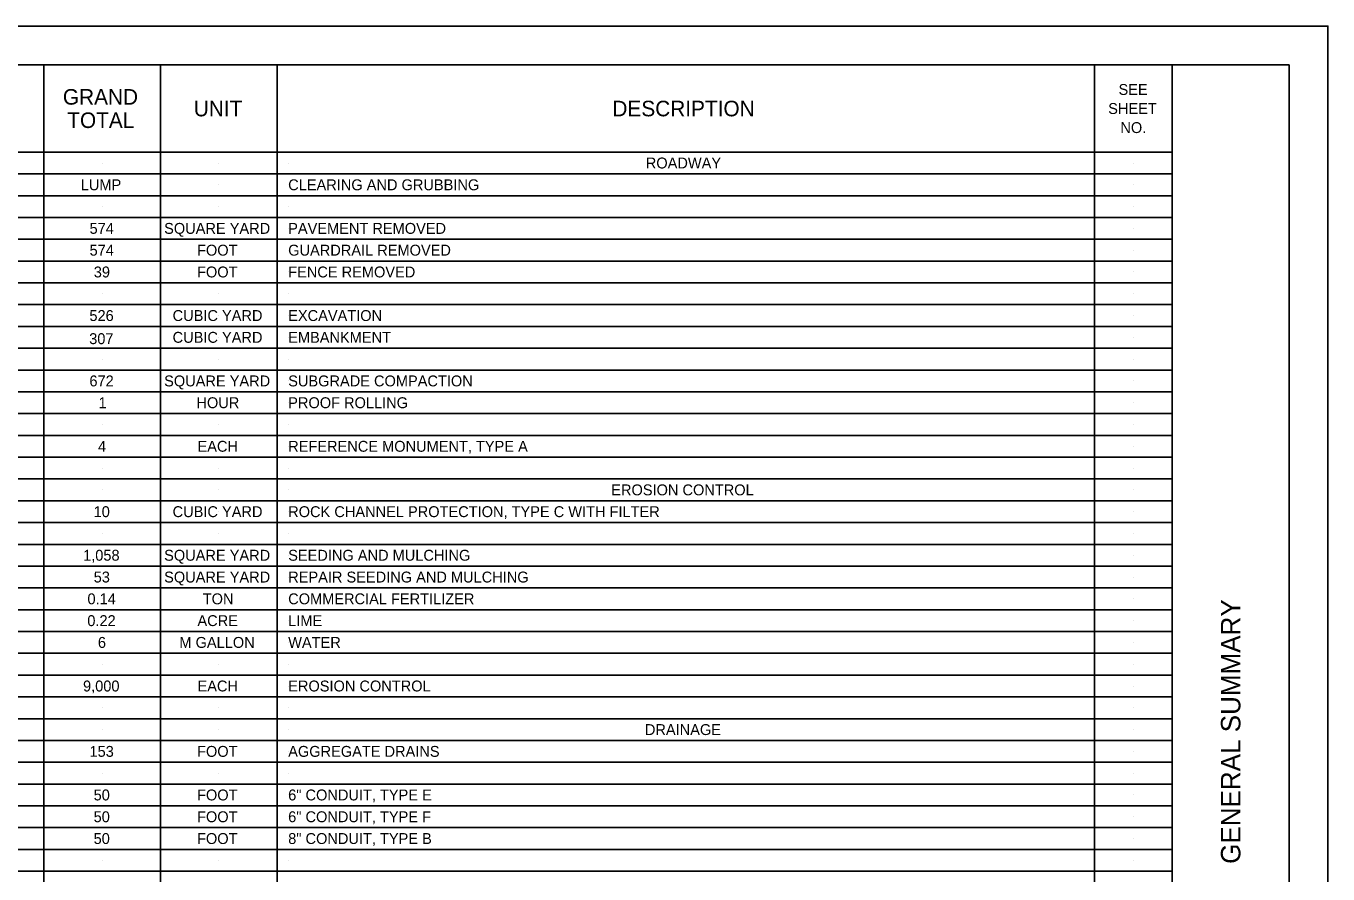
# Model space of a CAD drawing. Extents: x 0 to 34, y 0 to 22.
# Drawn here: x 17.27 to 34, y 11.1 to 22 of the extents above; entities that cross this region are included whole.
import ezdxf

# ---------------------------------------------------------------- set-up
doc = ezdxf.new("R2010")
doc.units = 0
for name, color, linetype in [('RD_P_Text', 7, 'Continuous'), ('SC_Scratch1', 7, 'Continuous'), ('SH_Border', 7, 'Continuous'), ('SH_Cut_Line', 7, 'Continuous'), ('SH_Data', 7, 'Continuous')]:
    doc.layers.add(name, color=color, linetype=linetype)

msp = doc.modelspace()

# ---------------------------------------------------------------- linework, layer by layer
at = {"layer": 'SC_Scratch1'}
for p, q in [((18.25, 20.24), (18.25, 20.24)), ((19.75, 20.24), (19.75, 20.24)), ((20.64, 20.24), (20.64, 20.24)), ((31.5, 20.24), (31.5, 20.24)), ((18.25, 19.96), (18.25, 19.96)), ((19.75, 19.96), (19.75, 19.96)), ((20.64, 19.96), (20.64, 19.96)), ((31.5, 19.96), (31.5, 19.96)), ((18.25, 19.68), (18.25, 19.68)), ((19.75, 19.68), (19.75, 19.68)), ((20.64, 19.68), (20.64, 19.68)), ((31.5, 19.68), (31.5, 19.68)), ((18.25, 19.4), (18.25, 19.4)), ((19.75, 19.4), (19.75, 19.4)), ((20.64, 19.4), (20.64, 19.4)), ((31.5, 19.4), (31.5, 19.4)), ((18.25, 19.12), (18.25, 19.12)), ((19.75, 19.12), (19.75, 19.12)), ((20.64, 19.12), (20.64, 19.12)), ((31.5, 19.12), (31.5, 19.12)), ((18.25, 18.84), (18.25, 18.84)), ((19.75, 18.84), (19.75, 18.84)), ((20.64, 18.84), (20.64, 18.84)), ((31.5, 18.84), (31.5, 18.84)), ((18.25, 18.56), (18.25, 18.56)), ((19.75, 18.56), (19.75, 18.56)), ((20.64, 18.56), (20.64, 18.56)), ((31.5, 18.56), (31.5, 18.56)), ((18.25, 18.28), (18.25, 18.28)), ((19.75, 18.28), (19.75, 18.28)), ((20.64, 18.28), (20.64, 18.28)), ((31.5, 18.28), (31.5, 18.28)), ((18.25, 18), (18.25, 18)), ((19.75, 18), (19.75, 18)), ((20.64, 18), (20.64, 18)), ((31.5, 18), (31.5, 18)), ((18.25, 17.72), (18.25, 17.72)), ((19.75, 17.72), (19.75, 17.72)), ((20.64, 17.72), (20.64, 17.72)), ((31.5, 17.72), (31.5, 17.72)), ((18.25, 17.44), (18.25, 17.44)), ((19.75, 17.44), (19.75, 17.44)), ((20.64, 17.44), (20.64, 17.44)), ((31.5, 17.44), (31.5, 17.44)), ((18.25, 17.16), (18.25, 17.16)), ((19.75, 17.16), (19.75, 17.16)), ((20.64, 17.16), (20.64, 17.16)), ((31.5, 17.16), (31.5, 17.16)), ((18.25, 16.88), (18.25, 16.88)), ((19.75, 16.88), (19.75, 16.88)), ((20.64, 16.88), (20.64, 16.88)), ((31.5, 16.88), (31.5, 16.88)), ((18.25, 16.6), (18.25, 16.6)), ((19.75, 16.6), (19.75, 16.6)), ((20.64, 16.6), (20.64, 16.6)), ((31.5, 16.6), (31.5, 16.6)), ((18.25, 16.32), (18.25, 16.32)), ((19.75, 16.32), (19.75, 16.32)), ((20.64, 16.32), (20.64, 16.32)), ((31.5, 16.32), (31.5, 16.32)), ((18.25, 16.04), (18.25, 16.04)), ((19.75, 16.04), (19.75, 16.04)), ((20.64, 16.04), (20.64, 16.04)), ((31.5, 16.04), (31.5, 16.04)), ((18.25, 15.76), (18.25, 15.76)), ((19.75, 15.76), (19.75, 15.76)), ((20.64, 15.76), (20.64, 15.76)), ((31.5, 15.76), (31.5, 15.76)), ((18.25, 15.48), (18.25, 15.48)), ((19.75, 15.48), (19.75, 15.48)), ((20.64, 15.48), (20.64, 15.48)), ((31.5, 15.48), (31.5, 15.48)), ((18.25, 15.2), (18.25, 15.2)), ((19.75, 15.2), (19.75, 15.2)), ((20.64, 15.2), (20.64, 15.2)), ((31.5, 15.2), (31.5, 15.2)), ((18.25, 14.92), (18.25, 14.92)), ((19.75, 14.92), (19.75, 14.92)), ((20.64, 14.92), (20.64, 14.92)), ((31.5, 14.92), (31.5, 14.92)), ((18.25, 14.64), (18.25, 14.64)), ((19.75, 14.64), (19.75, 14.64)), ((20.64, 14.64), (20.64, 14.64)), ((31.5, 14.64), (31.5, 14.64)), ((18.25, 14.36), (18.25, 14.36)), ((19.75, 14.36), (19.75, 14.36)), ((20.64, 14.36), (20.64, 14.36)), ((31.5, 14.36), (31.5, 14.36)), ((18.25, 14.08), (18.25, 14.08)), ((19.75, 14.08), (19.75, 14.08)), ((20.64, 14.08), (20.64, 14.08)), ((31.5, 14.08), (31.5, 14.08)), ((18.25, 13.8), (18.25, 13.8)), ((19.75, 13.8), (19.75, 13.8)), ((20.64, 13.8), (20.64, 13.8)), ((31.5, 13.8), (31.5, 13.8)), ((18.25, 13.52), (18.25, 13.52)), ((19.75, 13.52), (19.75, 13.52)), ((20.64, 13.52), (20.64, 13.52)), ((31.5, 13.52), (31.5, 13.52)), ((18.25, 13.24), (18.25, 13.24)), ((19.75, 13.24), (19.75, 13.24)), ((20.64, 13.24), (20.64, 13.24)), ((31.5, 13.24), (31.5, 13.24)), ((18.25, 12.96), (18.25, 12.96)), ((19.75, 12.96), (19.75, 12.96)), ((20.64, 12.96), (20.64, 12.96)), ((31.5, 12.96), (31.5, 12.96)), ((18.25, 12.68), (18.25, 12.68)), ((19.75, 12.68), (19.75, 12.68)), ((20.64, 12.68), (20.64, 12.68)), ((31.5, 12.68), (31.5, 12.68)), ((18.25, 12.4), (18.25, 12.4)), ((19.75, 12.4), (19.75, 12.4)), ((20.64, 12.4), (20.64, 12.4)), ((31.5, 12.4), (31.5, 12.4)), ((18.25, 12.12), (18.25, 12.12)), ((19.75, 12.12), (19.75, 12.12)), ((20.64, 12.12), (20.64, 12.12)), ((31.5, 12.12), (31.5, 12.12)), ((18.25, 11.84), (18.25, 11.84)), ((19.75, 11.84), (19.75, 11.84)), ((20.64, 11.84), (20.64, 11.84)), ((31.5, 11.84), (31.5, 11.84)), ((18.25, 11.56), (18.25, 11.56)), ((19.75, 11.56), (19.75, 11.56)), ((20.64, 11.56), (20.64, 11.56)), ((31.5, 11.56), (31.5, 11.56)), ((18.25, 11.28), (18.25, 11.28)), ((19.75, 11.28), (19.75, 11.28)), ((20.64, 11.28), (20.64, 11.28)), ((31.5, 11.28), (31.5, 11.28))]:
    msp.add_line(p, q, dxfattribs=at)
at = {"layer": 'SH_Border'}
msp.add_line((32, 0.5), (32, 21.5), dxfattribs=at)
msp.add_lwpolyline([(1.5, 21.5), (33.5, 21.5), (33.5, 0.5), (1.5, 0.5)], close=True, dxfattribs=at)
at = {"layer": 'SH_Cut_Line'}
msp.add_lwpolyline([(0, 0), (34, 0), (34, 22), (0, 22)], close=True, dxfattribs=at)
at = {"layer": 'SH_Data'}
for p, q in [((17.5, 21.5), (17.5, 0.5)), ((19, 21.5), (19, 0.5)), ((20.5, 21.5), (20.5, 0.5)), ((31, 21.5), (31, 0.5)), ((32, 20.38), (1.5, 20.38)), ((32, 20.1), (1.5, 20.1)), ((32, 19.82), (1.5, 19.82)), ((32, 19.54), (1.5, 19.54)), ((32, 19.26), (1.5, 19.26)), ((32, 18.98), (1.5, 18.98)), ((32, 18.7), (1.5, 18.7)), ((32, 18.42), (1.5, 18.42)), ((32, 18.14), (1.5, 18.14)), ((32, 17.86), (1.5, 17.86)), ((32, 17.58), (1.5, 17.58)), ((32, 17.3), (1.5, 17.3)), ((32, 17.02), (1.5, 17.02)), ((32, 16.74), (1.5, 16.74)), ((32, 16.46), (1.5, 16.46)), ((32, 16.18), (1.5, 16.18)), ((32, 15.9), (1.5, 15.9)), ((32, 15.62), (1.5, 15.62)), ((32, 15.34), (1.5, 15.34)), ((32, 15.06), (1.5, 15.06)), ((32, 14.78), (1.5, 14.78)), ((32, 14.5), (1.5, 14.5)), ((32, 14.22), (1.5, 14.22)), ((32, 13.94), (1.5, 13.94)), ((32, 13.66), (1.5, 13.66)), ((32, 13.38), (1.5, 13.38)), ((32, 13.1), (1.5, 13.1)), ((32, 12.82), (1.5, 12.82)), ((32, 12.54), (1.5, 12.54)), ((32, 12.26), (1.5, 12.26)), ((32, 11.98), (1.5, 11.98)), ((32, 11.7), (1.5, 11.7)), ((32, 11.42), (1.5, 11.42)), ((32, 11.14), (1.5, 11.14))]:
    msp.add_line(p, q, dxfattribs=at)

# ---------------------------------------------------------------- texts
at = {"layer": 'RD_P_Text'}
for s, p in [('ROADWAY', (25.235, 20.17)), ('LUMP', (17.975, 19.89)), ('CLEARING AND GRUBBING', (20.64, 19.89)), ('574', (18.088, 19.33)), ('SQUARE YARD', (19.046, 19.33)), ('PAVEMENT REMOVED', (20.64, 19.33)), ('574', (18.088, 19.05)), ('FOOT', (19.469, 19.05)), ('GUARDRAIL REMOVED', (20.64, 19.05)), ('39', (18.142, 18.77)), ('FOOT', (19.469, 18.77)), ('FENCE REMOVED', (20.64, 18.77)), ('526', (18.086, 18.21)), ('CUBIC YARD', (19.155, 18.21)), ('EXCAVATION', (20.64, 18.21)), ('CUBIC YARD', (19.155, 17.93)), ('EMBANKMENT', (20.64, 17.93)), ('307', (18.083, 17.913)), ('672', (18.086, 17.37)), ('SQUARE YARD', (19.046, 17.37)), ('SUBGRADE COMPACTION', (20.64, 17.37)), ('HOUR', (19.461, 17.09)), ('PROOF ROLLING', (20.64, 17.09)), ('1', (18.203, 17.09)), ('4', (18.197, 16.53)), ('EACH', (19.475, 16.53)), ('REFERENCE MONUMENT, TYPE A', (20.64, 16.53)), ('EROSION CONTROL', (24.791, 15.97)), ('10', (18.14, 15.69)), ('CUBIC YARD', (19.155, 15.69)), ('ROCK CHANNEL PROTECTION, TYPE C WITH FILTER', (20.64, 15.69)), ('1,058', (18.005, 15.13)), ('SQUARE YARD', (19.046, 15.13)), ('SEEDING AND MULCHING', (20.64, 15.13)), ('53', (18.141, 14.85)), ('SQUARE YARD', (19.046, 14.85)), ('REPAIR SEEDING AND MULCHING', (20.64, 14.85)), ('0.14', (18.061, 14.57)), ('TON', (19.542, 14.57)), ('COMMERCIAL FERTILIZER', (20.64, 14.57)), ('0.22', (18.059, 14.29)), ('ACRE', (19.474, 14.29)), ('LIME', (20.64, 14.29)), ('6', (18.195, 14.01)), ('M GALLON', (19.242, 14.01)), ('WATER', (20.64, 14.01)), ('9,000', (18.004, 13.45)), ('EACH', (19.475, 13.45)), ('EROSION CONTROL', (20.64, 13.45)), ('DRAINAGE', (25.223, 12.89)), ('153', (18.087, 12.61)), ('FOOT', (19.469, 12.61)), ('AGGREGATE DRAINS', (20.64, 12.61)), ('50', (18.14, 12.05)), ('FOOT', (19.469, 12.05)), ('6" CONDUIT, TYPE E', (20.64, 12.05)), ('50', (18.14, 11.77)), ('FOOT', (19.469, 11.77)), ('6" CONDUIT, TYPE F', (20.64, 11.77)), ('50', (18.14, 11.49)), ('FOOT', (19.469, 11.49)), ('8" CONDUIT, TYPE B', (20.64, 11.49))]:
    msp.add_text(s, height=0.14, dxfattribs=at).set_placement(p)
at = {"layer": 'SH_Data'}
for s, height, p in [('SEE', 0.14, (31.309, 21.115)), ('GRAND', 0.2, (17.745, 20.99)), ('UNIT', 0.2, (19.427, 20.84)), ('DESCRIPTION', 0.2, (24.806, 20.84)), ('SHEET', 0.14, (31.176, 20.87)), ('TOTAL', 0.2, (17.801, 20.69)), ('NO.', 0.14, (31.333, 20.625))]:
    msp.add_text(s, height=height, dxfattribs=at).set_placement(p)
msp.add_text('GENERAL SUMMARY', height=0.25, rotation=90, dxfattribs=at).set_placement((32.875, 11.235))

doc.saveas('drawing.dxf')
